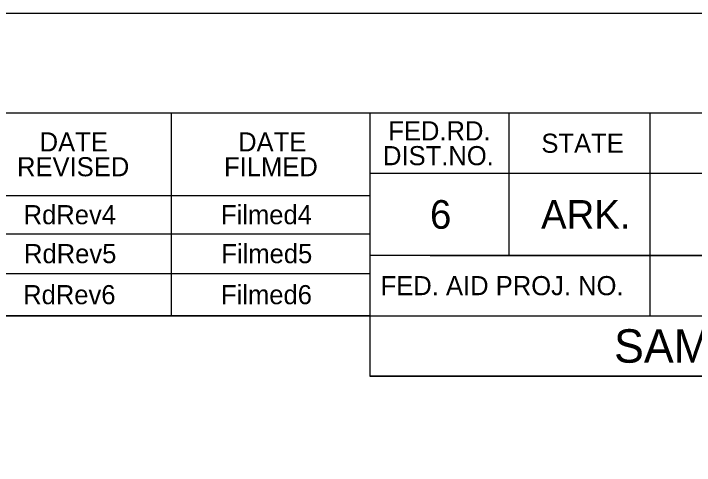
# Model space of a CAD drawing. Extents: x -0.25 to 1.42, y 0 to 0.92.
# Drawn here: x 1.1381 to 1.2805, y 0.8221 to 0.9167 of the extents above; entities that cross this region are included whole.
import ezdxf

# ---------------------------------------------------------------- set-up
doc = ezdxf.new("R2010")
doc.units = 0
for name, color, linetype in [('SHET_Annotations', 7, 'Continuous'), ('SHET_Border-Lines', 7, 'Continuous'), ('SHET_Border-Text', 7, 'Continuous')]:
    doc.layers.add(name, color=color, linetype=linetype)

msp = doc.modelspace()

# ---------------------------------------------------------------- linework, layer by layer
at = {"layer": 'SHET_Border-Lines'}
for p, q in [((1.17114, 0.85338), (1.17114, 0.89583)), ((1.21266, 0.89583), (1.21266, 0.84075)), ((1.24173, 0.89583), (1.24173, 0.86601)), ((1.27123, 0.89583), (1.27123, 0.85338)), ((1.39583, 0.8832), (1.21266, 0.8832)), ((1.04658, 0.87856), (1.21266, 0.87856)), ((1.04658, 0.87057), (1.21266, 0.87057)), ((1.39583, 0.86601), (1.21266, 0.86601)), ((1.22524, 0.86601), (1.39583, 0.86601)), ((1.04658, 0.86223), (1.21266, 0.86223)), ((1.21266, 0.85338), (1.04658, 0.85338)), ((1.21266, 0.85338), (1.39583, 0.85338)), ((1.39583, 0.84075), (1.21266, 0.84075))]:
    msp.add_line(p, q, dxfattribs=at)
for points in [[(0, 0), (1.41667, 0), (1.41667, 0.91667), (0, 0.91667)], [(0.02083, 0.02083), (1.39583, 0.02083), (1.39583, 0.89583), (0.02083, 0.89583)], [(1.04658, 0.85338), (1.21266, 0.85338), (1.21266, 0.84075), (1.39583, 0.84075), (1.39583, 0.89583), (1.04658, 0.89583)]]:
    msp.add_lwpolyline(points, close=True, dxfattribs=at)

# ---------------------------------------------------------------- texts
at = {"layer": 'SHET_Annotations'}
for s, height, p in [('6', 0.006, (1.22524, 0.87161)), ('ARK.', 0.006, (1.24847, 0.87161)), ('RdRev4', 0.004, (1.14023, 0.87256)), ('Filmed4', 0.004, (1.18151, 0.87256)), ('RdRev5', 0.004, (1.14031, 0.8644)), ('Filmed5', 0.004, (1.18159, 0.8644)), ('RdRev6', 0.004, (1.14013, 0.85581)), ('Filmed6', 0.004, (1.18152, 0.85581)), ('SAMPLE PROJECT', 0.007, (1.26374, 0.84356))]:
    msp.add_text(s, height=height, dxfattribs=at).set_placement(p)
at = {"layer": 'SHET_Border-Text'}
for s, p in [('FED.RD.', (1.21651, 0.89012)), ('DATE', (1.14358, 0.8878)), ('DATE', (1.1851, 0.8878)), ('STATE', (1.24854, 0.88752)), ('DIST.NO.', (1.21541, 0.88492)), ('REVISED', (1.13885, 0.8826)), ('FILMED', (1.18216, 0.8826)), ('FED. AID PROJ. NO.', (1.21491, 0.8577))]:
    msp.add_text(s, height=0.004, dxfattribs=at).set_placement(p)

doc.saveas('drawing.dxf')
